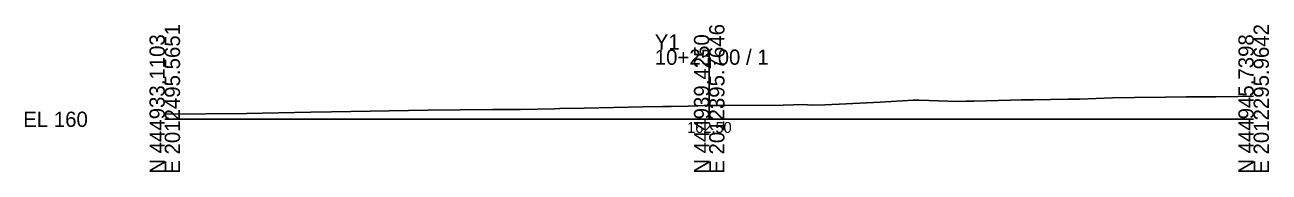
# Model space of a CAD drawing. Extents: x -26 to 3203, y -10 to 9517.
# Drawn here: x -25.7 to 202.8, y 490.3 to 517.3 of the extents above; entities that cross this region are included whole.
import ezdxf

# ---------------------------------------------------------------- set-up
doc = ezdxf.new("R2010")
doc.units = 0
for name, color, linetype in [('Default', 7, 'Continuous'), ('Exist Cross Section Cell', 7, 'Continuous'), ('Exist XS Center Line Elevation Label', 7, 'Continuous'), ('Exist XS Ground Line', 7, 'Continuous')]:
    doc.layers.add(name, color=color, linetype=linetype)

msp = doc.modelspace()

# ---------------------------------------------------------------- linework, layer by layer
at = {"layer": 'Exist Cross Section Cell'}
for p, q in [((100, 500), (100, 512.8)), ((0, 500), (100, 500)), ((100, 500), (200, 500))]:
    msp.add_line(p, q, dxfattribs=at)
at = {"layer": 'Exist XS Ground Line'}
msp.add_lwpolyline([(0, 500.91), (14.99, 501.05), (26.8, 501.29), (30.62, 501.36), (48.29, 501.68), (60.19, 501.78), (65.32, 501.81), (71.58, 501.89), (72.54, 501.96), (77.06, 502.04), (87.89, 502.28), (91.39, 502.34), (93, 502.37), (96.11, 502.43), (99.07, 502.5), (100, 502.5), (102.94, 502.5), (113.6, 502.62), (117.37, 502.69), (118.75, 502.6), (121.25, 502.68), (125.15, 502.84), (131.4, 503.15), (137.44, 503.49), (137.96, 503.51), (138.56, 503.52), (145.68, 503.28), (147.23, 503.31), (148.62, 503.34), (155.34, 503.51), (157.33, 503.55), (159.48, 503.59), (165.91, 503.68), (168.07, 503.72), (174.05, 503.94), (178.1, 504.02), (183.79, 504.03), (187.66, 504.11), (193.07, 504.12), (197.12, 504.2), (200, 504.27)], dxfattribs=at)

# ---------------------------------------------------------------- texts
at = {"layer": 'Default'}
msp.add_text('-', height=0.0001, dxfattribs=at).set_placement((0, 500))
at = {"layer": 'Exist Cross Section Cell'}
for s, p in [('E 2012495.5651', (2.8, 490)), ('E 2012395.7646', (102.8, 490)), ('E 2012295.9642', (202.8, 490)), ('N 444933.1103', (0, 490)), ('N 444939.4250', (100, 490)), ('N 444945.7398', (200, 490))]:
    msp.add_text(s, height=2.8, rotation=90, dxfattribs=at).set_placement(p)
for s, p in [('Y1', (90, 512.8)), ('10+25.00 / 1', (90, 510)), ('EL 160', (-26, 498.6))]:
    msp.add_text(s, height=2.8, dxfattribs=at).set_placement(p)
at = {"layer": 'Exist XS Center Line Elevation Label'}
msp.add_text('162.50', height=2, dxfattribs=at).set_placement((95.95, 497.5))

doc.saveas('drawing.dxf')
